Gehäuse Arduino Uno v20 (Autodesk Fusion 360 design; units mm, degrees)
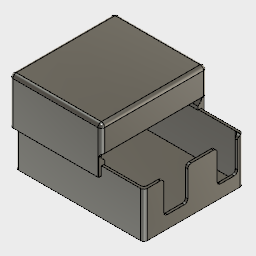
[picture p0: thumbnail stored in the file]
sketch "Skizze1"
  line L1 (-37.5, 29) -> (37.5, 29)
  line L2 (-37.5, -29) -> (-37.5, 29)
  line L3 (37.5, -29) -> (-37.5, -29)
  line L4 (37.5, 29) -> (37.5, -29)
  line L5 (-37.5, -29) -> (37.5, 29)
  line L6 (37.5, -29) -> (-37.5, 29)
  point P4 (-37.5, -29)
  point P5 (37.5, -29)
  point P3 (-37.5, 29)
  dimension "d1" distance P4 P5 = 75
  dimension "d2" distance P3 P4 = 58
extrude "Extrusion1" new body sketch "Skizze1" profile of L1 L2 L3 L4 blind 1.4
sketch "Skizze2" plane through (0, 0, 1.4) normal (0, 0, 1) x axis (-1, 0, 0)
  line L1 (-37.5, -29) -> (-37.5, 29)
  line L2 (37.5, -29) -> (-37.5, -29)
  line L3 (37.5, 29) -> (37.5, -29)
  line L4 (-37.5, 29) -> (37.5, 29)
  line L5 (-36.1, -27.6) -> (-36.1, 27.6)
  line L6 (36.1, -27.6) -> (-36.1, -27.6)
  line L7 (36.1, 27.6) -> (36.1, -27.6)
  line L8 (-36.1, 27.6) -> (36.1, 27.6)
  dimension "d5" = 1.4
extrude "Extrusion2" add sketch "Skizze2" along normal blind 25
sketch "Skizze4" plane through (0, 0, 1.4) normal (0, 0, 1) x axis (-1, 0, 0)
  line L1 (-36.1, -27.6) -> (-36.1, 27.6)
  line L2 (36.1, -27.6) -> (-36.1, -27.6)
  line L3 (36.1, 27.6) -> (36.1, -27.6)
  line L4 (-36.1, 27.6) -> (36.1, 27.6)
  line L5 (-33.4, -27.1) -> (-33.4, 25.9)
  line L6 (34.6, -22.1) -> (31.6, -25.1)
  line L7 (31.6, 15.9) -> (34.6, 12.9)
  line L8 (31.6, -27.1) -> (-33.4, -27.1)
  line L9 (34.6, 12.9) -> (34.6, -22.1)
  circle C1 centre (-18.4, 23.4) radius 2
  circle C2 centre (32.1, 7.9) radius 2
  circle C3 centre (32.1, -20.1) radius 2
  circle C4 centre (-19.4, -24.6) radius 2
  point P8 (31.6, -27.1)
  point P10 (-33.4, -27.1)
  point P12 (34.6, 12.9)
  point P7 (34.6, -22.1)
  point P17 (-18.4, 23.4)
  point P16 (32.1, -20.1)
  point P9 (32.1, 7.9)
  point P13 (-19.4, -24.6)
  dimension "d11" distance L5 L9 = 68
  dimension "d12" distance P8 P10 = 65
  dimension "d14" distance P12 L8 = 40
  dimension "d15" distance P7 L8 = 5
  dimension "d17" diameter C1 = 4
  dimension "d18" distance P17 L5 = 15
  dimension "d19" distance P17 L8 = 50.5
  dimension "d22" distance P16 L8 = 7
  dimension "d23" distance P9 L8 = 35
  dimension "d24" distance P9 L5 = 65.5
  dimension "d26" distance P13 L5 = 14
  dimension "d27" distance P13 L8 = 2.5
  dimension "d28" distance L2 L8 = 0.5
  dimension "d29" distance L3 L9 = 1.5
extrude "Extrusion4" add sketch "Skizze4" profile of C1 C2 C3 C4 along normal blind 3
sketch "Skizze5" plane through (0, 0, 4.4) normal (0, 0, 1) x axis (-1, 0, 0)
  circle C1 centre (32.1, -20.1) radius 2
  circle C2 centre (32.1, 7.9) radius 2
  circle C3 centre (32.1, -20.1) radius 2
  circle C4 centre (-19.4, -24.6) radius 2
  circle C5 centre (-18.4, 23.4) radius 2
  circle C6 centre (32.1, 7.9) radius 1.5
  circle C7 centre (32.1, -20.1) radius 1.5
  circle C8 centre (-19.4, -24.6) radius 1.5
  circle C9 centre (-18.4, 23.4) radius 1.5
  dimension "d32" diameter C9 = 3
extrude "Extrusion5" add sketch "Skizze5" profile of C6 C7 C8 C9 along normal blind 4
fillet "Abrundung1" radius 1
fillet "Abrundung2" radius 2
sketch "Skizze6" plane through (0, 0, 26.4) normal (0, 0, 1) x axis (-1, 0, 0)
  line L1 (34.1, 27.6) -> (-34.1, 27.6)
  line L2 (36.1, -25.6) -> (36.1, 25.6)
  line L3 (-34.1, -27.6) -> (34.1, -27.6)
  line L4 (-36.1, 25.6) -> (-36.1, -25.6)
  line L5 (-35.5, 29) -> (35.5, 29)
  line L6 (-37.5, -27) -> (-37.5, 27)
  line L7 (35.5, -29) -> (-35.5, -29)
  line L8 (37.5, 27) -> (37.5, -27)
  line L9 (36.1, -9) -> (37.5, -9)
  line L10 (36.1, 9) -> (37.5, 9)
  arc A1 centre (34.1, 25.6) radius 2 clockwise from (34.1, 27.6) to (36.1, 25.6)
  arc A2 centre (34.1, -25.6) radius 2 clockwise from (36.1, -25.6) to (34.1, -27.6)
  arc A3 centre (-34.1, -25.6) radius 2 clockwise from (-34.1, -27.6) to (-36.1, -25.6)
  arc A4 centre (-34.1, 25.6) radius 2 clockwise from (-36.1, 25.6) to (-34.1, 27.6)
  arc A5 centre (35.5, 27) radius 2 clockwise from (35.5, 29) to (37.5, 27)
  arc A6 centre (-35.5, 27) radius 2 clockwise from (-37.5, 27) to (-35.5, 29)
  arc A7 centre (-35.5, -27) radius 2 clockwise from (-35.5, -29) to (-37.5, -27)
  arc A8 centre (35.5, -27) radius 2 clockwise from (37.5, -27) to (35.5, -29)
  point P1 (0, 0)
  dimension "d37" distance L9 L10 = 18
  dimension "d38" distance P1 L9 = 9 (= "d37 / 2")
extrude "Extrusion6" cut sketch "Skizze6" profile of L2 L8 L9 L10 against normal blind 15
fillet "Abrundung3" radius 4
sketch "Skizze7" plane through (37.5, 0, 0) normal (1, 0, 0) x axis (0, 1, 0)
  line L1 (-27, 0) -> (-27, 26.4)
  line L2 (27, 0) -> (-27, 0)
  line L3 (27, 26.4) -> (27, 0)
  line L4 (-27, 26.4) -> (27, 26.4)
  line L5 (-17.4, 7.4) -> (-3.4, 7.4)
  line L6 (-17.4, 26.4) -> (-17.4, 7.4)
  line L7 (-3.4, 7.4) -> (-3.4, 26.4)
  line L8 (-17.4, 26.4) -> (-3.4, 7.4)
  line L9 (-3.4, 26.4) -> (-17.4, 7.4)
  line L10 (-9.9, 4.4) -> (-5.9, 4.4)
  line L11 (25.6, 7.4) -> (25.6, 26.4)
  line L12 (13.6, 7.4) -> (25.6, 7.4)
  line L13 (13.6, 26.4) -> (13.6, 7.4)
  line L14 (25.6, 7.4) -> (13.6, 26.4)
  line L15 (25.6, 26.4) -> (13.6, 7.4)
  point P10 (-10.4, 16.9)
  point P11 (-23.4, 7.4)
  point P6 (-3.4, 7.4)
  point P7 (-17.4, 7.4)
  point P16 (25.6, 7.4)
  point P17 (13.6, 7.4)
  point P18 (19.6, 16.9)
  dimension "d42" distance P10 P11 = 13
  dimension "d44" distance L5 L10 = 3
  dimension "d45" distance P6 P7 = 14
  dimension "d50" distance P16 P17 = 12
  dimension "d51" distance P10 P18 = 30
extrude "Extrusion7" cut sketch "Skizze7" profile of L4 L5 L6 L7 L11 L12 L13 to an object
fillet "Abrundung4" radius 2
fillet "Abrundung5" radius 1
sketch "Skizze8" plane through (0, 0, 26.4) normal (0, 0, 1) x axis (-1, 0, 0)
  line L1 (-37.4079, -27.6) -> (-34.1, -27.6)
  line L2 (35.5, -29) -> (-35.5, -29)
  line L3 (37.5, -9) -> (37.5, -27)
  line L4 (36.1, -9) -> (37.5, -9)
  line L5 (36.1, -25.6) -> (36.1, -9)
  line L6 (-34.1, -27.6) -> (34.1, -27.6)
  line L7 (-35.5, 29) -> (35.5, 29)
  line L8 (-36.1, 19.4) -> (-37.5, 19.4)
  line L9 (-36.1, 25.6) -> (-36.1, 19.4)
  line L10 (34.1, 27.6) -> (-34.1, 27.6)
  line L11 (36.1, 9) -> (36.1, 25.6)
  line L12 (37.5, 9) -> (36.1, 9)
  line L13 (37.5, 27) -> (37.5, 9)
  line L14 (-35.5, 29) -> (35.5, 29)
  line L15 (-37.5, 19.4) -> (-37.5, 27)
  line L16 (37.5, -9) -> (37.5, -27)
  line L17 (35.5, -29) -> (-35.5, -29)
  line L18 (35.5, -29) -> (-35.5, -29)
  line L19 (-12.8553, 30.75) -> (39.05, 30.75)
  line L20 (-12.8553, 29.15) -> (-12.8553, 30.75)
  line L21 (39.05, -30.75) -> (39.05, 30.75)
  line L22 (-12.8553, -30.75) -> (39.05, -30.75)
  line L23 (-12.8553, -29.15) -> (-12.8553, -30.75)
  line L24 (34.9447, -29.15) -> (-12.8553, -29.15)
  line L25 (35.5, -29.15) -> (34.9447, -29.15)
  line L26 (37.65, 27) -> (37.65, -27)
  line L27 (35.5, 29.15) -> (-12.8553, 29.15)
  arc A1 centre (-35.5, -27) radius 2 clockwise from (-35.5, -29) to (-37.4079, -27.6)
  arc A2 centre (35.5, -27) radius 2 clockwise from (37.5, -27) to (35.5, -29)
  arc A3 centre (34.1, -25.6) radius 2 clockwise from (36.1, -25.6) to (34.1, -27.6)
  arc A4 centre (35.5, 27) radius 2 clockwise from (35.5, 29) to (37.5, 27)
  arc A5 centre (-34.1, 25.6) radius 2 clockwise from (-36.1, 25.6) to (-34.1, 27.6)
  arc A6 centre (34.1, 25.6) radius 2 clockwise from (34.1, 27.6) to (36.1, 25.6)
  arc A7 centre (35.5, 27) radius 2 clockwise from (35.5, 29) to (37.5, 27)
  arc A8 centre (-35.5, 27) radius 2 clockwise from (-37.5, 27) to (-35.5, 29)
  arc A9 centre (35.5, -27) radius 2 clockwise from (37.5, -27) to (35.5, -29)
  arc A10 centre (35.5, -27) radius 2 clockwise from (37.5, -27) to (35.5, -29)
  arc A11 centre (35.5, 27) radius 2.15 clockwise from (35.5, 29.15) to (37.65, 27)
  arc A12 centre (35.5, -27) radius 2.15 clockwise from (37.65, -27) to (35.5, -29.15)
  point P45 (-12.8553, 30.75)
  point P46 (-12.8553, 29.15)
  dimension "d59" distance P45 P46 = 1.6
  dimension "d82" distance L2 L24 = 0.15
  dimension "d83" distance L3 L26 = 0.15
  dimension "d84" distance L7 L27 = 0.15
  dimension "d85" distance L21 L26 = 1.4
extrude "Extrusion8" new body sketch "Skizze8" profile of L19 L20 L21 L22 L23 against normal blind 5
extrude "Extrusion9" add of existing geometry blind 20
sketch "Skizze9" plane through (12.8553, 0, 0) normal (1, 0, 0) x axis (0, 1, 0)
  line L1 (-30.75, 21.4) -> (-30.75, 46.4)
  line L2 (-29.15, 21.4) -> (-30.75, 21.4)
  line L3 (-30.75, 46.4) -> (-29.15, 46.4)
  line L4 (-27.15, 26.4) -> (-29.15, 26.4)
  line L5 (-27.15, 28.4) -> (-27.15, 26.4)
  line L6 (-29.15, 30.4) -> (-27.15, 28.4)
  line L7 (-30.75, 46.4) -> (30.75, 46.4)
  line L8 (0, 0) -> (0, 46.4)
  line L9 (29.15, 30.4) -> (27.15, 28.4)
  line L10 (27.15, 28.4) -> (27.15, 26.4)
  line L11 (27.15, 26.4) -> (29.15, 26.4)
  line L12 (29.15, 46.4) -> (29.15, 21.4)
  line L13 (-29.15, 46.4) -> (-29.15, 21.4)
  point P6 (-29.15, 26.4)
  point P7 (-27.15, 26.4)
  point P8 (-27.15, 28.4)
  dimension "d67" distance P6 P7 = 2
  dimension "d69" distance L2 L4 = 5
  dimension "d71" distance P7 P8 = 2
  dimension "d92" angle L5 L6 = 135
extrude "Extrusion10" new body sketch "Skizze9" profile of L4 L5 L6 L9 L10 L11 L12 L13 against normal blind 45
sketch "Skizze10" plane through (0, 0, 46.4) normal (0, 0, 1) x axis (-1, 0, 0)
  line L1 (-12.8553, -30.75) -> (-12.8553, -29.15)
  line L2 (39.05, -30.75) -> (-12.8553, -30.75)
  line L3 (39.05, 30.75) -> (39.05, -30.75)
  line L4 (-12.8553, 30.75) -> (39.05, 30.75)
  line L5 (-12.8553, 29.15) -> (-12.8553, 30.75)
  line L6 (39.05, 30.75) -> (-12.8553, 30.75)
  line L7 (39.05, -30.75) -> (39.05, 30.75)
  line L8 (-12.8553, -30.75) -> (39.05, -30.75)
  line L9 (-12.8553, 30.75) -> (-12.8553, -30.75)
  line L10 (35.5, 29.15) -> (-12.8553, 29.15)
  line L11 (37.65, -27) -> (37.65, 27)
  line L12 (34.9447, -29.15) -> (35.5, -29.15)
  line L13 (-12.8553, -29.15) -> (34.9447, -29.15)
  arc A1 centre (35.5, 27) radius 2.15 clockwise from (35.5, 29.15) to (37.65, 27)
  arc A2 centre (35.5, -27) radius 2.15 clockwise from (37.65, -27) to (35.5, -29.15)
extrude "Extrusion11" add sketch "Skizze10" profile of L1 L2 L3 L4 L5 L6 L7 L8 L9 along normal blind 2
fillet "Abrundung6" radius 2
sketch "Skizze11" plane through (12.8553, 0, 0) normal (1, 0, 0) x axis (0, 1, 0)
  line L1 (-28.75, 48.4) -> (28.75, 48.4)
  line L2 (-30.75, 21.4) -> (-30.75, 46.4)
  line L3 (-29.15, 21.4) -> (-30.75, 21.4)
  line L4 (29.15, 46.4) -> (-29.15, 46.4)
  line L5 (28.75, 48.4) -> (-28.75, 48.4)
  line L6 (-30.75, 46.4) -> (-30.75, 21.4)
  line L7 (30.75, 46.4) -> (30.75, 21.4)
  line L8 (30.75, 33.4) -> (-30.75, 33.4)
  line L9 (-29.15, 46.4) -> (-29.15, 21.4)
  line L10 (29.15, 21.4) -> (29.15, 46.4)
  line L11 (30.75, 21.4) -> (29.15, 21.4)
  line L12 (30.75, 46.4) -> (30.75, 21.4)
  arc A1 centre (28.75, 46.4) radius 2 clockwise from (28.75, 48.4) to (30.75, 46.4)
  arc A2 centre (-28.75, 46.4) radius 2 clockwise from (-30.75, 46.4) to (-28.75, 48.4)
  arc A3 centre (-28.75, 46.4) radius 2 clockwise from (-30.75, 46.4) to (-28.75, 48.4)
  arc A4 centre (28.75, 46.4) radius 2 clockwise from (28.75, 48.4) to (30.75, 46.4)
  dimension "d77" distance L1 L8 = 15
extrude "Extrusion12" add sketch "Skizze11" profile of A1 L1 A2 L2 L4 A3 L5 L6 L7 A4 L8 L9 L10 L12 along normal blind 1.6
fillet "Abrundung7" radius 2
fillet "Abrundung8" radius 3
fillet "Abrundung9" radius 2
fillet "Abrundung10" radius 2
combine "Kombinieren1"
combine "Kombinieren2"
sketch "Skizze3" plane through (0, -29, 0) normal (0, -1, 0) x axis (1, 0, 0)
  line L1 (37.5, 0) -> (-37.5, 0)
  line L2 (37.5, 42) -> (37.5, 0)
  line L3 (-37.5, 42) -> (37.5, 42)
  line L4 (-37.5, 0) -> (-37.5, 42)
  line L5 (-11.5, 42) -> (-37.5, 42)
  line L6 (-11.5, 23) -> (-11.5, 42)
  line L7 (-37.5, 23) -> (-11.5, 23)
  line L8 (-37.5, 42) -> (-37.5, 23)
  point P8 (-11.5, 23)
  point P9 (-37.5, 23)
  dimension "d8" distance P8 P9 = 26
  dimension "d9" distance L1 L7 = 23
extrude "Extrusion3" cut sketch "Skizze3" profile of L3 L4 L5 L6 L7 L8 no distance stored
